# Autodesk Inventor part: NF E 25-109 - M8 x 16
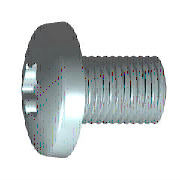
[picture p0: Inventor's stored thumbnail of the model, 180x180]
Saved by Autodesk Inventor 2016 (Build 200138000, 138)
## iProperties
IsCustomPart: 0
Created: 2015-02
Part Number: NF E 25-109 - M8 x 16
Material: Steel, Mild
Description: Hexagon Lobular Socket Pan Head Screw
Document SubType Name: Modeling
Standard: NF E 25-109
Designer: stank
Standards Organization: AFNOR
Language: en-US
Size Designation: M8 x 16
Categories: <MemberInstance><Categories><Category DisplayName="Fasteners" InternalName="e4da775c-781d-43d5-af7c-5136215cf5a6" Mnemonic="FSTN"><Category DisplayName="Bolts"
Density: 7.85 g/cm^3
Appearance: Semi-Polished
Author: stank
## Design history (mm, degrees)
sketch "Sketch1"
  geometry: L1 (-1.47, 0)-(16, 0); L2 (16, 0)-(16, 4); L3 (16, 4)-(1.25, 4); L4 (1.25, 4)-(0.483, 3.662); L5 (0.483, 3.662)-(0, 3.662); L6 (0, 3.662)-(0, 8); L7 (0, 8)-(-3.247, 8); L8 (-5.563, 3.344)-(-3.4, 3.344); L9 (-3.4, 3.344)-(-1.47, 0); L10 (-6, 0)-(-1.47, 0); L11 (-18.19, 0)-(55.532, 0) reference; L12 (0, -2)-(0, 12) reference; L13 (1.25, 4)-(0, 4); A1 r 13 centre (7, 0) between (-3.247, 8) and (-5.563, 3.344); A2 r 13 centre (7, 0) between (-5.563, 3.344) and (-6, 0)
  constraints: 22 end point, 4 perpendicular, 4 point on circle, 3 collinear, 2 centre point, 2 parallel, 2 point on line, 1 coincident, 1 horizontal
  dimensions: "d0" = 16 distance between parallel lines of L2 L6 (= NLG); "d1" = 14.75 distance from line of L3.end L2 (= GEL); "d2" = 0.76681 horizontal distance of L4.end L3.end (= GAL); "d3" = 6 distance from line of L10.start L6 (= KOH); "d4" = 2.6 horizontal distance of L10.start L8.end (= INTI); "d5" = 60 deg angle of L9 L1; "d6" = 8 diameter of L3 L1 (= GD); "d7" = 16 diameter of L6.end L1 (= KOD); "d8" = 0 deg angle of L7 L1 (computed from KEWI); "d9" = 6.687 diameter of L8 L1 (= E0); "d10" = 7.32342 diameter of L5 L1 (= BDM); "d11" = 13 radius of A1 (= KR); "d21" = 0.43732 horizontal distance of L8.start L10.start (derived)
revolve "Body" sketch "Sketch1" stored, may be unused: angle "d12" = 90 deg
node "IDS_WORKPLANE{1}"
sketch "Sketch2"
  geometry: L1 (0, -11.2)-(0, 11.2) reference; L2 (11.2, 0)-(-11.2, 0) reference; L3 (0, 0)-(2.233, 3.868); L4 (0, 0)-(3.82, 2.206); C1 r 2.39 at (0, 0); C2 r 3.662 at (0, 0); C3 r 3.662 at (0, 0) reference; A1 r 0.548 centre (3.114, 0) between (3.662, 0) and (3.137, 0.547); A2 r 0.548 centre (1.557, 2.697) between (2.043, 2.443) and (1.095, 2.991); A3 r 1.297 centre (3.193, 1.844) between (2.043, 2.443) and (3.137, 0.547); A4 r 0.548 centre (-1.557, 2.697) between (-1.095, 2.991) and (-2.043, 2.443); A5 r 1.297 centre (0, 3.687) between (-1.095, 2.991) and (1.095, 2.991); A6 r 1.297 centre (-3.193, 1.844) between (-3.137, 0.547) and (-2.043, 2.443); A7 r 0.548 centre (-3.114, 0) between (-3.137, 0.547) and (-3.662, 0); A8 r 0.548 centre (-3.114, 0) between (-3.662, 0) and (-3.137, -0.547); A9 r 1.297 centre (-3.193, -1.844) between (-2.043, -2.443) and (-3.137, -0.547); A10 r 0.548 centre (-1.557, -2.697) between (-2.043, -2.443) and (-1.095, -2.991); A11 r 1.297 centre (0, -3.687) between (1.095, -2.991) and (-1.095, -2.991); A12 r 0.548 centre (1.557, -2.697) between (1.095, -2.991) and (2.043, -2.443); A13 r 1.297 centre (3.193, -1.844) between (3.137, -0.547) and (2.043, -2.443); A14 r 0.548 centre (3.114, 0) between (3.137, -0.547) and (3.662, 0); 2 further points
  constraints: 28 point on circle, 16 centre point, 16 symmetric about line, 10 tangent, 4 end point, 3 point on line, 1 coincident, 10 other
  dimensions: "d14" = 4.78 diameter of C1 (= SW); "d15" = 30 deg angle of L4 L2; "d16" = 60 deg angle of L3 L2; "d27" = 0.548 radius of A4 (= RRK); "d28" = 0.548 radius of A1 (= RRK)
extrude "Slot" join sketch "Sketch2" taper "d17" = 0 deg; stored distance "d19" = 10
workplane "Work Plane2"
body "Solid1"
fillet "Fillet1" dims "d18" = 0.8 (= RR)
feature "Thread" dims "d20" = 14.75 (= GEL), "d22" = 0
other parameters: "GD" = 8 (= NND) [user parameter; used in 1 equation term], "NLG" = 16 [user parameter; used in 1 equation term], "GEL" = 14.75 [user parameter; used in 2 equation terms], "KOD" = 16 [user parameter; used in 1 equation term], "KOH" = 6 [user parameter; used in 2 equation terms], "INTI" = 2.6 [user parameter; used in 1 equation term], "GAL" = 0.76681 (= 0.61345 x PTC) [user parameter; used in 2 equation terms], "KR" = 13 [user parameter; used in 1 equation term], "BDM" = 7.32342 [user parameter; used in 1 equation term], "KEWI" = 0 [user parameter; used in 1 equation term], "SW" = 4.78 [user parameter; used in 1 equation term], "d13" = -5.56268 (= -KOH + d21), "RR" = 0.8 [user parameter; used in 1 equation term], "RRK" = 0.548 [user parameter; used in 2 equation terms], "d26" = 0, "E0" = 6.687 [user parameter; used in 1 equation term], "d32" = 0, "d33" = 0, "GUL" = 0.76681 (= 0.61345 x PTC) [user parameter], "SPD" = 7.0592 (= NND - 1.2269 x GAL) [user parameter], "PHH" = 0 [user parameter], "GD1" = 6.46637 (= THREADDIA - 1.2269 x PTC) [user parameter], "THREADDIA" = 8 [user parameter; used in 1 equation term], "FAWI" = 90 deg [user parameter], "ANG" = 120 deg [user parameter], "TPU" = 8 (computed from PTC) [user parameter], "PTC" = 1.25 [user parameter; used in 4 equation terms], "NND" = 8 [user parameter; used in 2 equation terms], "TOA" = 30 deg [user parameter]
